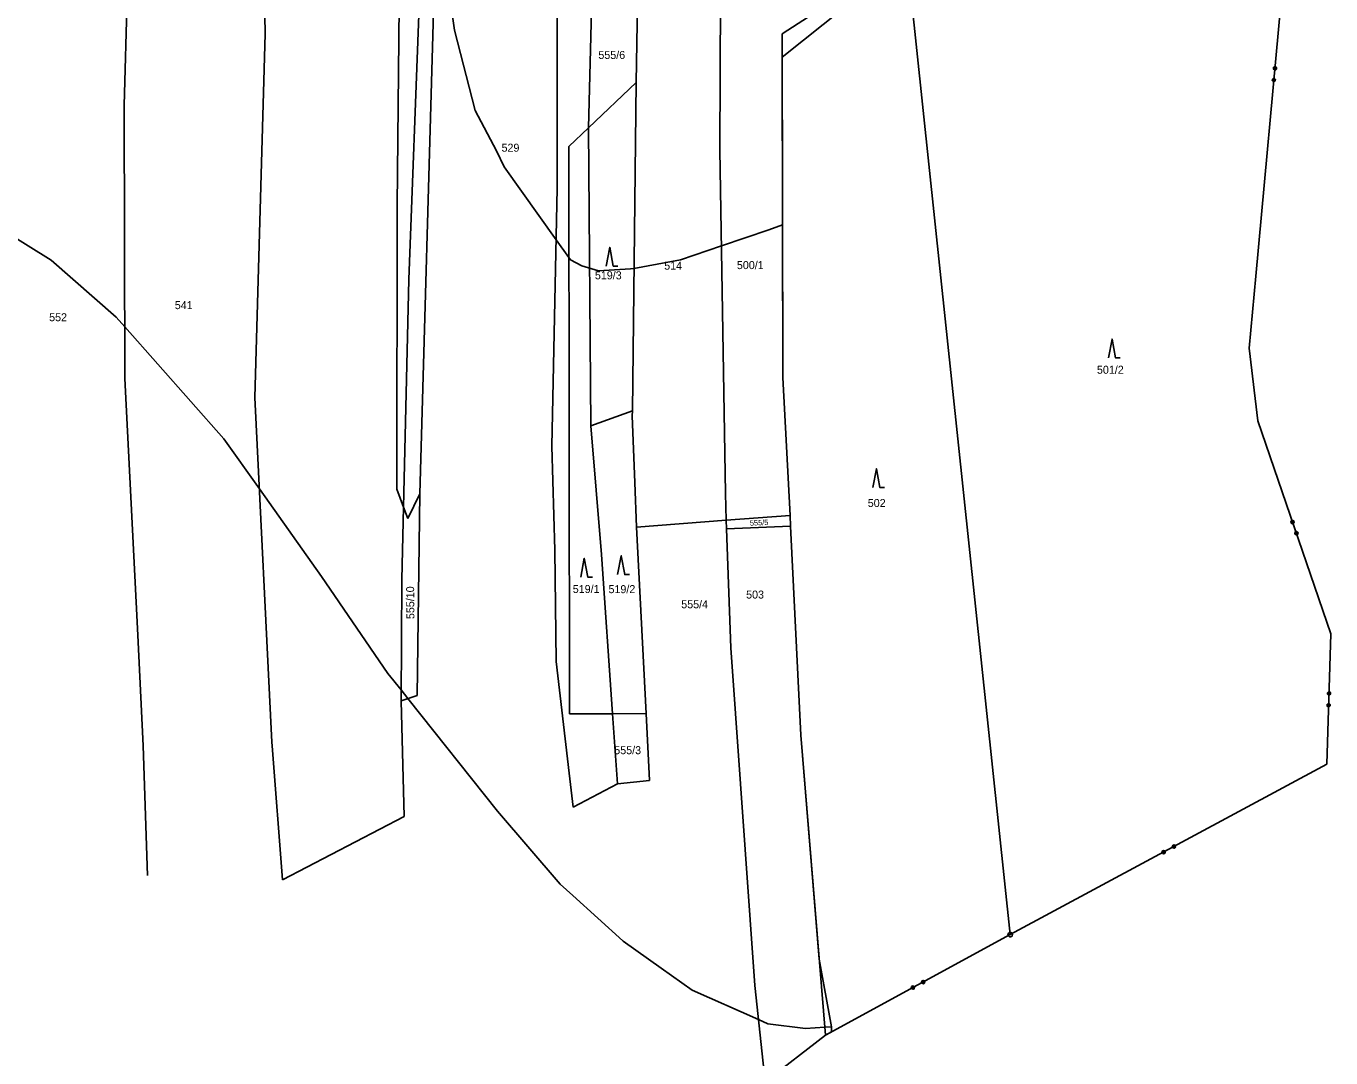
# Model space of a CAD drawing. Extents: x -760978 to -760029, y -1177282 to -1176414.
# Drawn here: x -760612.3 to -760335.2, y -1176992.4 to -1176773.3 of the extents above; entities that cross this region are included whole.
import ezdxf

# ---------------------------------------------------------------- set-up
doc = ezdxf.new("R2010")
doc.units = 0
for name, color, linetype in [('1', 7, 'Continuous'), ('11', 7, 'Continuous'), ('2', 7, 'Continuous'), ('3', 7, 'Continuous'), ('8', 7, 'Continuous')]:
    doc.layers.add(name, color=color, linetype=linetype)

msp = doc.modelspace()

# ---------------------------------------------------------------- linework, layer by layer
at = {"layer": '1'}
for p, q in [((-760499.51, -1176807.73), (-760499.51, -1176721.27)), ((-760562.19, -1176728.12), (-760561.57, -1176774.94)), ((-760343.22, -1176740.55), (-760351.15, -1176826.4)), ((-760590.35, -1176748.16), (-760591.5, -1176790.17)), ((-760451.75, -1176774.96), (-760425.3, -1176757.87)), ((-760425.3, -1176757.87), (-760403.29, -1176966.24)), ((-760464.83, -1176765.57), (-760464.97, -1176799.58)), ((-760482.48, -1176768.6), (-760482.77, -1176785.31)), ((-760533.09, -1176768.95), (-760533.53, -1176811.46)), ((-760528.83, -1176769.08), (-760531.06, -1176827.1)), ((-760528.7, -1176872.66), (-760525.79, -1176770.28)), ((-760492.21, -1176769.91), (-760492.85, -1176794.9)), ((-760561.57, -1176774.94), (-760563.73, -1176852.16)), ((-760451.63, -1176847.91), (-760451.75, -1176774.96)), ((-760482.77, -1176785.31), (-760492.85, -1176794.9)), ((-760482.77, -1176785.31), (-760483.56, -1176855)), ((-760591.5, -1176790.17), (-760591.35, -1176848.16)), ((-760492.85, -1176794.9), (-760497.08, -1176798.92)), ((-760492.85, -1176794.9), (-760492.36, -1176858.19)), ((-760497.08, -1176798.92), (-760496.98, -1176860.58)), ((-760464.97, -1176799.58), (-760463.81, -1176872.6)), ((-760500.68, -1176862.5), (-760499.51, -1176807.73)), ((-760533.53, -1176811.46), (-760533.61, -1176871.67)), ((-760351.15, -1176826.4), (-760352.57, -1176841.73)), ((-760531.06, -1176827.1), (-760532.16, -1176875.5)), ((-760352.57, -1176841.73), (-760351.27, -1176852.38)), ((-760591.35, -1176848.16), (-760588.65, -1176901.22)), ((-760450.07, -1176877.21), (-760451.63, -1176847.91)), ((-760563.73, -1176852.16), (-760560.16, -1176925.39)), ((-760351.27, -1176852.38), (-760350.69, -1176857.14)), ((-760492.36, -1176858.19), (-760483.56, -1176855)), ((-760483.56, -1176855), (-760483.57, -1176856.1)), ((-760483.57, -1176856.1), (-760483.06, -1176870.23)), ((-760350.69, -1176857.14), (-760335.19, -1176902.39)), ((-760492.36, -1176858.19), (-760490.13, -1176885.53)), ((-760500.06, -1176884.6), (-760500.68, -1176862.5)), ((-760496.98, -1176860.58), (-760496.88, -1176919.34)), ((-760483.06, -1176870.23), (-760482.71, -1176879.7)), ((-760533.61, -1176871.67), (-760532.16, -1176875.5)), ((-760531.26, -1176877.89), (-760528.7, -1176872.66)), ((-760529.29, -1176915.47), (-760528.7, -1176872.66)), ((-760463.81, -1176872.6), (-760463.61, -1176878.24)), ((-760532.16, -1176875.5), (-760532.51, -1176890.82)), ((-760532.16, -1176875.5), (-760531.26, -1176877.89)), ((-760482.71, -1176879.7), (-760463.61, -1176878.24)), ((-760463.61, -1176878.24), (-760450.07, -1176877.21)), ((-760463.61, -1176878.24), (-760463.55, -1176880.07)), ((-760463.55, -1176880.07), (-760449.96, -1176879.49)), ((-760450.07, -1176877.21), (-760449.96, -1176879.49)), ((-760449.96, -1176879.49), (-760447.79, -1176923.86)), ((-760480.6, -1176919.31), (-760482.71, -1176879.7)), ((-760463.55, -1176880.07), (-760462.66, -1176905.31)), ((-760499.73, -1176908.23), (-760500.06, -1176884.6)), ((-760490.13, -1176885.53), (-760487.77, -1176919.32)), ((-760532.51, -1176890.82), (-760532.7, -1176916.57)), ((-760588.65, -1176901.22), (-760587.92, -1176917.28)), ((-760335.19, -1176902.39), (-760336.05, -1176930.06)), ((-760462.66, -1176905.31), (-760457.58, -1176977.01)), ((-760496.96, -1176931.94), (-760499.73, -1176908.23)), ((-760529.29, -1176915.47), (-760532.7, -1176916.57)), ((-760587.92, -1176917.28), (-760587.45, -1176926.17)), ((-760532.01, -1176941.14), (-760532.7, -1176916.57)), ((-760496.88, -1176919.34), (-760487.77, -1176919.32)), ((-760487.77, -1176919.32), (-760480.6, -1176919.31)), ((-760487.77, -1176919.32), (-760486.73, -1176934.23)), ((-760479.95, -1176933.54), (-760480.6, -1176919.31)), ((-760447.79, -1176923.86), (-760442.56, -1176987.58)), ((-760587.45, -1176926.17), (-760586.53, -1176953.66)), ((-760560.1, -1176926.18), (-760560.16, -1176925.39)), ((-760557.87, -1176954.58), (-760560.1, -1176926.18)), ((-760496.96, -1176931.94), (-760496.12, -1176939.18)), ((-760403.29, -1176966.24), (-760336.05, -1176930.06)), ((-760496.12, -1176939.18), (-760486.73, -1176934.23)), ((-760486.73, -1176934.23), (-760479.95, -1176933.54)), ((-760557.87, -1176954.58), (-760532.01, -1176941.14)), ((-760442.56, -1176987.58), (-760403.29, -1176966.24)), ((-760457.58, -1176977.01), (-760455.34, -1176997.47)), ((-760442.56, -1176987.58), (-760455.34, -1176997.47))]:
    msp.add_line(p, q, dxfattribs=at)
for points in [[(-760346.77, -1176782.44), (-760346.97, -1176782.61), (-760347.24, -1176782.59), (-760347.41, -1176782.38), (-760347.39, -1176782.11), (-760347.18, -1176781.94), (-760346.91, -1176781.96), (-760346.74, -1176782.17), (-760346.77, -1176782.44), (-760346.81, -1176782.43), (-760346.78, -1176782.19), (-760346.86, -1176782.1), (-760346.89, -1176782.5), (-760346.98, -1176782.57), (-760346.93, -1176782.01), (-760347.01, -1176782.01), (-760347.06, -1176782.56), (-760347.14, -1176782.56), (-760347.09, -1176782), (-760347.17, -1176781.99), (-760347.22, -1176782.55), (-760347.29, -1176782.46), (-760347.25, -1176782.06), (-760347.34, -1176782.13), (-760347.36, -1176782.37)], [(-760347, -1176784.93), (-760347.21, -1176785.1), (-760347.47, -1176785.08), (-760347.65, -1176784.87), (-760347.62, -1176784.6), (-760347.41, -1176784.43), (-760347.15, -1176784.45), (-760346.97, -1176784.66), (-760347, -1176784.93), (-760347.04, -1176784.89), (-760347.01, -1176784.66), (-760347.09, -1176784.57), (-760347.12, -1176784.97), (-760347.21, -1176785.04), (-760347.16, -1176784.48), (-760347.24, -1176784.47), (-760347.29, -1176785.03), (-760347.37, -1176785.02), (-760347.32, -1176784.47), (-760347.4, -1176784.46), (-760347.45, -1176785.02), (-760347.52, -1176784.93), (-760347.48, -1176784.53), (-760347.57, -1176784.6), (-760347.59, -1176784.84)], [(-760342.98, -1176878.65), (-760343.1, -1176878.89), (-760343.36, -1176878.98), (-760343.6, -1176878.86), (-760343.69, -1176878.6), (-760343.57, -1176878.36), (-760343.31, -1176878.28), (-760343.07, -1176878.39), (-760342.98, -1176878.65), (-760343.02, -1176878.65), (-760343.1, -1176878.43), (-760343.2, -1176878.38), (-760343.07, -1176878.75), (-760343.12, -1176878.86), (-760343.31, -1176878.33), (-760343.38, -1176878.35), (-760343.2, -1176878.88), (-760343.28, -1176878.91), (-760343.46, -1176878.38), (-760343.53, -1176878.4), (-760343.35, -1176878.93), (-760343.45, -1176878.88), (-760343.58, -1176878.51), (-760343.63, -1176878.61), (-760343.55, -1176878.83)], [(-760342.17, -1176881.01), (-760342.29, -1176881.26), (-760342.55, -1176881.34), (-760342.79, -1176881.22), (-760342.88, -1176880.97), (-760342.76, -1176880.73), (-760342.5, -1176880.64), (-760342.26, -1176880.76), (-760342.17, -1176881.01), (-760342.22, -1176881), (-760342.3, -1176880.77), (-760342.4, -1176880.72), (-760342.27, -1176881.1), (-760342.32, -1176881.2), (-760342.5, -1176880.67), (-760342.58, -1176880.7), (-760342.4, -1176881.23), (-760342.47, -1176881.25), (-760342.65, -1176880.72), (-760342.73, -1176880.75), (-760342.55, -1176881.28), (-760342.65, -1176881.23), (-760342.78, -1176880.85), (-760342.83, -1176880.95), (-760342.75, -1176881.18)], [(-760335.27, -1176915.17), (-760335.46, -1176915.35), (-760335.73, -1176915.34), (-760335.92, -1176915.15), (-760335.91, -1176914.88), (-760335.71, -1176914.69), (-760335.44, -1176914.7), (-760335.26, -1176914.9), (-760335.27, -1176915.17), (-760335.31, -1176915.15), (-760335.3, -1176914.91), (-760335.38, -1176914.83), (-760335.39, -1176915.23), (-760335.47, -1176915.31), (-760335.45, -1176914.75), (-760335.53, -1176914.75), (-760335.55, -1176915.31), (-760335.63, -1176915.3), (-760335.61, -1176914.74), (-760335.69, -1176914.74), (-760335.71, -1176915.3), (-760335.79, -1176915.22), (-760335.78, -1176914.82), (-760335.86, -1176914.9), (-760335.87, -1176915.14)], [(-760335.35, -1176917.66), (-760335.54, -1176917.85), (-760335.81, -1176917.84), (-760335.99, -1176917.64), (-760335.99, -1176917.37), (-760335.79, -1176917.19), (-760335.52, -1176917.2), (-760335.34, -1176917.39), (-760335.35, -1176917.66), (-760335.38, -1176917.63), (-760335.38, -1176917.39), (-760335.45, -1176917.31), (-760335.47, -1176917.71), (-760335.55, -1176917.79), (-760335.53, -1176917.23), (-760335.61, -1176917.23), (-760335.63, -1176917.79), (-760335.71, -1176917.78), (-760335.69, -1176917.22), (-760335.77, -1176917.22), (-760335.79, -1176917.78), (-760335.87, -1176917.7), (-760335.85, -1176917.3), (-760335.94, -1176917.38), (-760335.94, -1176917.62)], [(-760370.76, -1176948.38), (-760370.51, -1176948.45), (-760370.38, -1176948.69), (-760370.46, -1176948.95), (-760370.69, -1176949.08), (-760370.95, -1176949), (-760371.08, -1176948.76), (-760371, -1176948.5), (-760370.76, -1176948.38), (-760370.75, -1176948.42), (-760370.96, -1176948.53), (-760371, -1176948.64), (-760370.65, -1176948.45), (-760370.54, -1176948.48), (-760371.03, -1176948.75), (-760370.99, -1176948.82), (-760370.5, -1176948.55), (-760370.46, -1176948.62), (-760370.95, -1176948.89), (-760370.92, -1176948.96), (-760370.42, -1176948.69), (-760370.46, -1176948.8), (-760370.81, -1176948.99), (-760370.7, -1176949.02), (-760370.49, -1176948.91)], [(-760368.56, -1176947.19), (-760368.31, -1176947.27), (-760368.18, -1176947.51), (-760368.25, -1176947.76), (-760368.49, -1176947.89), (-760368.75, -1176947.81), (-760368.88, -1176947.58), (-760368.8, -1176947.32), (-760368.56, -1176947.19), (-760368.57, -1176947.24), (-760368.78, -1176947.35), (-760368.81, -1176947.46), (-760368.46, -1176947.27), (-760368.35, -1176947.3), (-760368.85, -1176947.57), (-760368.81, -1176947.64), (-760368.32, -1176947.38), (-760368.28, -1176947.45), (-760368.77, -1176947.71), (-760368.73, -1176947.78), (-760368.24, -1176947.52), (-760368.27, -1176947.62), (-760368.62, -1176947.81), (-760368.52, -1176947.85), (-760368.3, -1176947.73)], [(-760421.82, -1176975.95), (-760421.56, -1176976.02), (-760421.43, -1176976.26), (-760421.51, -1176976.52), (-760421.75, -1176976.65), (-760422.01, -1176976.57), (-760422.13, -1176976.33), (-760422.06, -1176976.07), (-760421.82, -1176975.95), (-760421.83, -1176976), (-760422.04, -1176976.11), (-760422.07, -1176976.22), (-760421.72, -1176976.03), (-760421.61, -1176976.06), (-760422.1, -1176976.33), (-760422.07, -1176976.4), (-760421.57, -1176976.13), (-760421.54, -1176976.2), (-760422.03, -1176976.47), (-760421.99, -1176976.54), (-760421.5, -1176976.27), (-760421.53, -1176976.38), (-760421.88, -1176976.57), (-760421.77, -1176976.6), (-760421.56, -1176976.49)], [(-760424.02, -1176977.14), (-760423.76, -1176977.22), (-760423.63, -1176977.45), (-760423.71, -1176977.71), (-760423.94, -1176977.84), (-760424.2, -1176977.76), (-760424.33, -1176977.53), (-760424.26, -1176977.27), (-760424.02, -1176977.14), (-760424.01, -1176977.18), (-760424.22, -1176977.29), (-760424.25, -1176977.4), (-760423.9, -1176977.21), (-760423.79, -1176977.24), (-760424.28, -1176977.51), (-760424.24, -1176977.58), (-760423.75, -1176977.31), (-760423.71, -1176977.38), (-760424.21, -1176977.65), (-760424.17, -1176977.72), (-760423.68, -1176977.45), (-760423.71, -1176977.56), (-760424.06, -1176977.75), (-760423.95, -1176977.79), (-760423.74, -1176977.67)]]:
    msp.add_lwpolyline(points, dxfattribs=at)
at = {"layer": '11'}
msp.add_line((-760441.23, -1176986.86), (-760441.25, -1176985.81), dxfattribs=at)
for points in [[(-760451.68, -1176815.55), (-760451.74, -1176779.89), (-760438.52, -1176769.41), (-760427.39, -1176763.26), (-760424.8, -1176762.59), (-760392.44, -1176754.17), (-760398.23, -1176744.75), (-760400.26, -1176739.63), (-760406.46, -1176729.34), (-760363.88, -1176709.5), (-760355.13, -1176712.14), (-760346.91, -1176731.76), (-760347.17, -1176735.96)], [(-760523.24, -1176760.62), (-760521.34, -1176774.21), (-760516.95, -1176791.24), (-760512.43, -1176799.79), (-760510.79, -1176803.21), (-760499.74, -1176818.68), (-760497.04, -1176822.46), (-760496.69, -1176822.96), (-760494.3, -1176824.23), (-760490.73, -1176825.26), (-760483.99, -1176824.89), (-760483.22, -1176824.76), (-760473.35, -1176822.98), (-760464.65, -1176820), (-760454.58, -1176816.55), (-760451.68, -1176815.55)], [(-760441.25, -1176985.81), (-760443.88, -1176971.44), (-760447.79, -1176923.86), (-760449.96, -1176879.49), (-760450.07, -1176877.21), (-760451.63, -1176847.91), (-760451.68, -1176815.55)], [(-760617.32, -1176816.58), (-760607.01, -1176823.01), (-760593.21, -1176835.13), (-760591.38, -1176837.2), (-760570.3, -1176860.98), (-760562.78, -1176871.56), (-760549.56, -1176890.17), (-760535.48, -1176910.77), (-760532.68, -1176914.28), (-760531.23, -1176916.1), (-760512.2, -1176940.01), (-760498.88, -1176955.5), (-760496.21, -1176957.92), (-760485.59, -1176967.53), (-760485.5, -1176967.62), (-760477.43, -1176973.36), (-760470.83, -1176978.06), (-760456.79, -1176984.27), (-760454.82, -1176985.14), (-760446.77, -1176986.13), (-760442.7, -1176985.9), (-760441.25, -1176985.81)], [(-760441.23, -1176986.86), (-760442.56, -1176987.58), (-760455.34, -1176997.47), (-760471.8, -1177010.19), (-760469.2, -1177110.41), (-760464.61, -1177142.53), (-760457.6, -1177191.53), (-760457.2, -1177194.65), (-760446, -1177281.92), (-760465.17, -1177280.51), (-760471.4, -1177280.32), (-760484.01, -1177279.94), (-760517.78, -1177278.91), (-760550.26, -1177277.92), (-760563.79, -1177275.5), (-760578.01, -1177273.25), (-760585.39, -1177272.09), (-760594.18, -1177268.52), (-760608.31, -1177262.06), (-760609.64, -1177261.45), (-760620.04, -1177255.81)]]:
    msp.add_lwpolyline(points, dxfattribs=at)
at = {"layer": '3'}
for points in [[(-760489.12, -1176824.27), (-760488.37, -1176820.27), (-760487.62, -1176824.27), (-760486.62, -1176824.27)], [(-760382.43, -1176843.79), (-760381.68, -1176839.79), (-760380.93, -1176843.79), (-760379.93, -1176843.79)], [(-760432.48, -1176871.33), (-760431.73, -1176867.33), (-760430.98, -1176871.33), (-760429.98, -1176871.33)], [(-760494.54, -1176890.32), (-760493.79, -1176886.32), (-760493.04, -1176890.32), (-760492.04, -1176890.32)], [(-760486.69, -1176889.8), (-760485.94, -1176885.8), (-760485.19, -1176889.8), (-760484.19, -1176889.8)]]:
    msp.add_lwpolyline(points, dxfattribs=at)
at = {"layer": '8'}
msp.add_line((-760403.41, -1176966.24), (-760403.17, -1176966.24), dxfattribs=at)
msp.add_lwpolyline([(-760403.14, -1176965.76), (-760402.89, -1176965.94), (-760402.79, -1176966.23), (-760402.89, -1176966.52), (-760403.14, -1176966.7), (-760403.45, -1176966.7), (-760403.7, -1176966.52), (-760403.8, -1176966.23), (-760403.7, -1176965.94), (-760403.45, -1176965.76)], close=True, dxfattribs=at)

# ---------------------------------------------------------------- texts
at = {"layer": '2'}
for s, p in [('555/6', (-760490.78, -1176780.3)), ('529', (-760511.35, -1176800)), ('514', (-760476.8, -1176825.05)), ('500/1', (-760461.36, -1176824.92)), ('519/3', (-760491.52, -1176827.09)), ('541', (-760580.75, -1176833.42)), ('552', (-760607.44, -1176835.99)), ('501/2', (-760384.88, -1176847.14)), ('502', (-760433.56, -1176875.44)), ('519/1', (-760496.22, -1176893.7)), ('519/2', (-760488.63, -1176893.73)), ('503', (-760459.4, -1176894.88)), ('555/4', (-760473.18, -1176896.94)), ('555/3', (-760487.4, -1176927.92))]:
    msp.add_text(s, height=1.7, dxfattribs=at).set_placement(p)
for s, height, rotation, p in [('555/5', 1.14, 2.1199, (-760458.59, -1176879.4)), ('555/10', 1.7, 90.47, (-760529.86, -1176899.23))]:
    msp.add_text(s, height=height, rotation=rotation, dxfattribs=at).set_placement(p)

doc.saveas('drawing.dxf')
